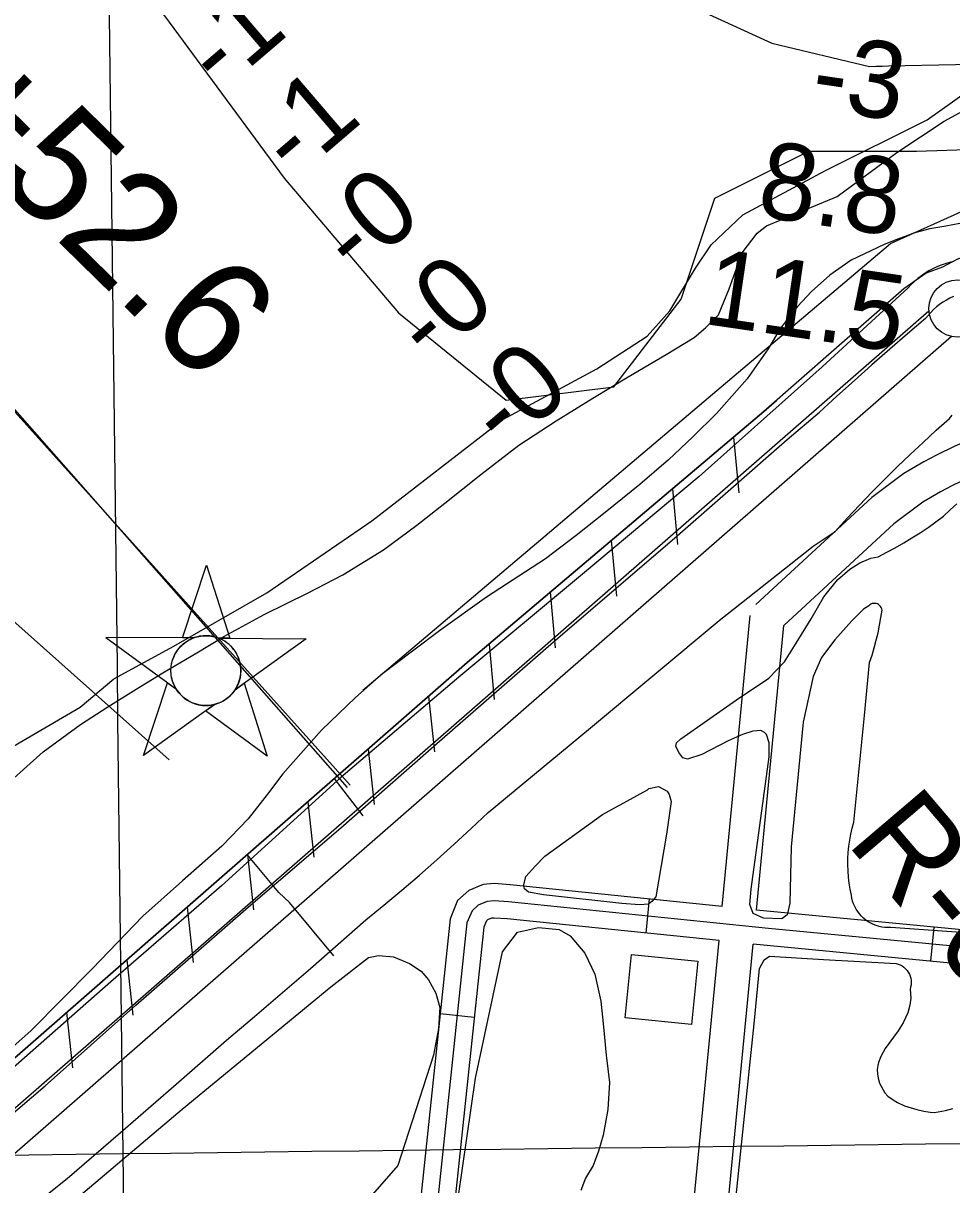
# Model space of a CAD drawing. Extents: x 3704301 to 3742427, y 506229 to 532009.
# Drawn here: x 3713691 to 3714502, y 517742 to 518757 of the extents above; entities that cross this region are included whole.
import ezdxf

# ---------------------------------------------------------------- set-up
doc = ezdxf.new("R2010")
doc.units = 0
for name, color, linetype in [('V-BLDG-OTLN', 7, 'Continuous'), ('V-CHAN-NAID', 7, 'Continuous'), ('V-FLOD-BASE', 7, 'Continuous'), ('V-GRID-MAJR', 7, 'Continuous'), ('V-LEVE-TOET', 7, 'Continuous'), ('V-RIVR-EDGE', 7, 'Continuous'), ('V-RIVR-RANG', 7, 'Continuous'), ('V-RIVR-RANG-IDEN', 7, 'Continuous'), ('V-ROAD-CNTR', 7, 'Continuous'), ('V-RRAP-FSHR', 7, 'Continuous'), ('V-SITE-VEGE', 7, 'Continuous'), ('V-SURV-IDEN', 7, 'Continuous'), ('V-SURV-LINE', 7, 'Continuous'), ('V-TOPO-DPTH', 7, 'Continuous'), ('V-TOPO-MINR', 7, 'Continuous'), ('V-TOPO-WATR', 7, 'Continuous'), ('V-UTIL-LINE', 7, 'Continuous')]:
    doc.layers.add(name, color=color, linetype=linetype)

msp = doc.modelspace()

# ---------------------------------------------------------------- linework, layer by layer
at = {"layer": 'V-BLDG-OTLN'}
msp.add_lwpolyline([(3714280.505, 517937.333), (3714274.965, 517882.015), (3714216.769, 517887.843), (3714222.307, 517943.162)], close=True, dxfattribs=at)
at = {"layer": 'V-CHAN-NAID'}
for points in [[(3713839.534, 518219.94), (3713829.947, 518220.00800000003), (3713851.073, 518283.492), (3713871.2970000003, 518219.715), (3713861.71, 518219.783), (3713860.133, 518220.36100000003), (3713858.038, 518220.981), (3713855.998, 518221.43200000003), (3713853.9620000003, 518221.74), (3713852.795, 518221.854), (3713851.261, 518221.935), (3713849.539, 518221.933), (3713848.169, 518221.863), (3713846.2630000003, 518221.662), (3713844.897, 518221.443), (3713843.113, 518221.059), (3713841.583, 518220.639), (3713840.551, 518220.308)], [(3713839.534, 518219.94), (3713763.043, 518220.482), (3713824.608, 518175.083), (3713823.495, 518176.992), (3713822.685, 518178.62), (3713821.86, 518180.588), (3713821.164, 518182.642), (3713820.799, 518183.965), (3713820.438, 518185.591), (3713820.194, 518187.036), (3713820.006, 518188.634), (3713819.897, 518190.37), (3713819.8850000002, 518191.951), (3713819.992, 518194.025), (3713820.1750000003, 518195.643), (3713820.5670000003, 518197.846), (3713821.048, 518199.76900000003), (3713821.651, 518201.656), (3713822.306, 518203.335), (3713823.0330000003, 518204.923), (3713823.847, 518206.458), (3713824.9080000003, 518208.195), (3713825.9390000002, 518209.66500000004), (3713826.9390000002, 518210.934), (3713827.941, 518212.08), (3713829.25, 518213.417), (3713830.301, 518214.382), (3713832.018, 518215.77900000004), (3713833.23, 518216.64900000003), (3713834.917, 518217.719), (3713836.648, 518218.664), (3713838.094, 518219.348)], [(3713861.71, 518219.783), (3713938.202, 518219.24), (3713875.9990000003, 518174.718), (3713876.91, 518176.207), (3713877.8880000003, 518178.054), (3713878.603, 518179.639), (3713879.342, 518181.594), (3713879.887, 518183.379), (3713880.285, 518185.018), (3713880.646, 518187.028), (3713880.832, 518188.601), (3713880.9560000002, 518190.80700000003), (3713880.926, 518192.869), (3713880.738, 518195.08900000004), (3713880.472, 518196.847), (3713879.981, 518199.079), (3713879.341, 518201.219), (3713878.591, 518203.201), (3713877.943, 518204.64400000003), (3713876.936, 518206.56), (3713875.8740000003, 518208.282), (3713874.66, 518209.984), (3713873.399, 518211.523), (3713872.127, 518212.889), (3713870.495, 518214.42100000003), (3713868.752, 518215.833), (3713867.069, 518217.01), (3713865.182, 518218.142), (3713863.71, 518218.903)], [(3713857.968, 518161.81200000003), (3713795.765, 518117.29000000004), (3713816.8910000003, 518180.773), (3713824.608, 518175.083), (3713825.2430000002, 518174.119), (3713826.626, 518172.26), (3713827.839, 518170.844), (3713829.305, 518169.341), (3713830.694, 518168.09), (3713832.148, 518166.934), (3713833.551, 518165.947), (3713835.2290000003, 518164.911), (3713836.943, 518164), (3713838.734, 518163.189), (3713840.18, 518162.63300000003), (3713841.808, 518162.104), (3713844.034, 518161.54000000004), (3713845.566, 518161.253), (3713847.591, 518160.996), (3713849.128, 518160.892), (3713850.989, 518160.87), (3713852.6780000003, 518160.94800000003), (3713854.3880000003, 518161.124), (3713856.29, 518161.435)], [(3713875.9990000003, 518174.718), (3713883.795, 518180.299), (3713904.019, 518116.522), (3713850.171, 518156.232), (3713857.968, 518161.81200000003), (3713859.634, 518162.288), (3713861.2460000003, 518162.848), (3713863.404, 518163.762), (3713865.139, 518164.646), (3713867.005, 518165.76), (3713868.744, 518166.972), (3713870.296, 518168.217), (3713871.583, 518169.385), (3713872.967, 518170.805), (3713874.171, 518172.207), (3713875.29, 518173.679)]]:
    msp.add_lwpolyline(points, close=True, dxfattribs=at)
msp.add_circle((3713850.4199147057, 518191.4060339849), 30.540600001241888, dxfattribs=at)
at = {"layer": 'V-FLOD-BASE'}
msp.add_line((3714401.961, 518431.208), (3714386.821, 518417.227), dxfattribs=at)
for points in [[(3714503.901, 518518.445), (3714500.72, 518516.979), (3714497.632, 518515.32800000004), (3714494.646, 518513.49700000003), (3714491.772, 518511.496), (3714489.02, 518509.329), (3714486.4, 518507.005), (3714483.92, 518504.531), (3714481.592, 518501.916), (3714479.419, 518499.169), (3714463.698, 518485.843), (3714448.091, 518472.381), (3714432.597, 518458.787), (3714417.219, 518445.061), (3714401.961, 518431.208)], [(3713614.086, 517746.863), (3713709.848, 517828.39400000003), (3713789.091, 517899.015), (3713887.6780000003, 517984.808), (3713968.342, 518054.012), (3714057.023, 518131.746), (3714154.194, 518216.588), (3714259.861, 518307.124), (3714358.4450000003, 518393.39), (3714386.821, 518417.227)]]:
    msp.add_lwpolyline(points, dxfattribs=at)
at = {"layer": 'V-GRID-MAJR'}
for points in [[(3713850.364, 511710.695), (3713778.102, 517769.291), (3713705.816, 523829.819), (3713633.5300000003, 529890.361), (3713633.507, 529892.279)], [(3708498.534, 517706.704), (3713778.102, 517769.291), (3719057.661, 517832.646), (3724337.211, 517896.76900000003), (3729616.752, 517961.659), (3734896.2830000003, 518027.318), (3740175.804, 518093.744), (3740175.805, 518093.744)]]:
    msp.add_spline(points, degree=3, dxfattribs=at)
at = {"layer": 'V-LEVE-TOET'}
for points in [[(3714492.9620000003, 518545.749), (3714489.335, 518544.264), (3714485.792, 518542.591), (3714482.343, 518540.731), (3714479.001, 518538.69200000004), (3714475.767, 518536.476), (3714472.6580000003, 518534.092), (3714469.681, 518531.54600000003), (3714466.84, 518528.847), (3714464.149, 518526), (3714389.018, 518456.804)], [(3714504.241, 518549.016), (3714500.4250000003, 518548.12700000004), (3714496.663, 518547.03500000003), (3714492.9620000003, 518545.749)], [(3714389.018, 518456.804), (3714281.4760000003, 518361.064), (3714181.466, 518277.16000000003), (3714071.5470000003, 518185.668), (3713968.238, 518097.972), (3713863.9990000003, 518003.185), (3713767.298, 517919.288), (3713657.393, 517823.069)], [(3714400.569, 518313.094), (3714411.061, 518324.659), (3714421.71, 518336.079), (3714432.5160000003, 518347.353), (3714443.474, 518358.478), (3714454.585, 518369.451), (3714465.845, 518380.271), (3714477.252, 518390.93700000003), (3714488.805, 518401.445), (3714500.4990000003, 518411.791), (3714502.7430000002, 518414.57)], [(3713673.179, 517702.569), (3713691.721, 517717.755), (3713710.411, 517732.75800000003), (3713729.247, 517747.582), (3713775.853, 517787.614), (3713822.24, 517827.90400000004), (3713868.4020000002, 517868.451), (3713892.997, 517889.199), (3713917.464, 517910.099), (3713941.807, 517931.14400000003), (3713966.02, 517952.33900000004), (3713990.105, 517973.677), (3714005.907, 517986.495), (3714021.543, 517999.515), (3714037.0160000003, 518012.73000000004), (3714052.3170000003, 518026.141), (3714067.4450000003, 518039.746), (3714082.4020000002, 518053.541), (3714097.18, 518067.527), (3714184.832, 518140.05700000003), (3714298.9960000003, 518235.342), (3714381.088, 518300.294), (3714400.569, 518313.094)]]:
    msp.add_lwpolyline(points, dxfattribs=at)
at = {"layer": 'V-RIVR-EDGE'}
msp.add_lwpolyline([(3713663.058686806, 518114.16552429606), (3713740.613165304, 518159.59857843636), (3713770.08985192, 518184.1390829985), (3713822.389202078, 518212.82544010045), (3713903.548587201, 518259.4502336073), (3713995.553865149, 518322.25702741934), (3714109.83492302, 518410.8227848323), (3714192.189016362, 518455.0433176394), (3714236.083845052, 518483.75045670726), (3714255.949426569, 518505.91342024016), (3714278.25341059, 518543.0785201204), (3714292.111309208, 518563.4553590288), (3714319.7914802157, 518589.8012857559), (3714391.926723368, 518628.6441471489), (3714480.884369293, 518672.8483512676), (3714527.1908808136, 518705.7518133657), (3714592.1029508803, 518736.808289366), (3714644.9833264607, 518757.68896353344)], dxfattribs=at)
at = {"layer": 'V-ROAD-CNTR'}
for p, q in [((3714235.1894906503, 517961.969049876), (3714238.2454845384, 517991.8129901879)), ((3714484.0729928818, 517937.40209901), (3714486.939987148, 517967.265039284)), ((3714085.00979101, 517888.21919737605), (3714055.1748506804, 517891.36019109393))]:
    msp.add_line(p, q, dxfattribs=at)
for points in [[(3715084.1797926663, 518468.53703673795), (3714839.3422823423, 518438.433096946), (3714653.624653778, 518425.268123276), (3714635.862689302, 518423.7071263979), (3714619.9017212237, 518421.65613049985), (3714600.441760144, 518418.315137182), (3714584.0347929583, 518414.76614428), (3714566.069828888, 518410.0871536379), (3714555.014850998, 518406.78616023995), (3714540.1858806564, 518401.838170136), (3714521.4529181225, 518394.697184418), (3714505.1089508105, 518387.6171985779), (3714488.981983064, 518379.80921419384), (3714477.9370051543, 518373.96522588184), (3714460.407040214, 518363.82424616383), (3714432.547095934, 518342.70728839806), (3714331.0492989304, 518249.1234755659)], [(3714825.8863092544, 518407.404159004), (3714655.99864903, 518395.36218308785), (3714639.08868285, 518393.8751860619), (3714624.3537123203, 518391.982189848), (3714606.1537487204, 518388.85719609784), (3714590.990779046, 518385.57620265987), (3714574.14381274, 518381.18921143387), (3714564.0568329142, 518378.17821745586), (3714550.2818604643, 518373.5802266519), (3714532.762895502, 518366.903240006), (3714517.6129258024, 518360.34125313), (3714502.5379559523, 518353.04126773), (3714492.4689760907, 518347.71327838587), (3714477.0430069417, 518338.790296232), (3714451.8210573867, 518319.6713344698), (3714355.598249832, 518230.95151190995)], [(3714301.781357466, 517985.3070031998), (3714326.2863084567, 518239.53449474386)], [(3714331.6192977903, 517982.17500946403), (3714355.598249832, 518230.95151190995)], [(3714301.781357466, 517985.3070031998), (3714116.2937284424, 518004.30196520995), (3714102.251756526, 518005.25796329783), (3714092.82977537, 518004.48196485), (3714080.307800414, 517999.34897511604), (3714070.435820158, 517990.3749930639), (3714063.9338331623, 517974.581024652), (3714036.2598885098, 517711.6615504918)], [(3715033.26789449, 517903.01216779), (3714888.08318486, 517913.93414594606), (3714759.820441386, 517926.00112181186), (3714342.0352769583, 517966.1060416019), (3714115.0197309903, 517989.353995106), (3714102.3587563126, 517990.215993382), (3714096.372768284, 517989.7229943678), (3714088.4417841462, 517986.47200087), (3714083.021794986, 517981.5450107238), (3714078.6258037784, 517970.86603208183), (3714051.177858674, 517710.09155363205)], [(3714298.9033632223, 517955.4440629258), (3714113.745733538, 517974.406025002), (3714102.465756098, 517975.1740234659), (3714099.915761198, 517974.96402388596), (3714096.575767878, 517973.595026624), (3714095.6077698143, 517972.715028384), (3714093.317774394, 517967.15103951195), (3714066.0958288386, 517708.521556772)], [(3714780.0354009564, 517939.165095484), (3714761.239438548, 517940.9340919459), (3714331.6192977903, 517982.17500946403)], [(3714214.8315313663, 516863.4722468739), (3714201.6745576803, 516901.517170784), (3714201.1185587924, 516916.40414100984), (3714201.8425573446, 516948.47907685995), (3714298.9033632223, 517955.4440629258)], [(3714243.183474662, 516873.278227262), (3714231.4864980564, 516907.101159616), (3714231.130498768, 516916.6261405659), (3714231.810497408, 516946.69908042), (3714328.740303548, 517952.31306918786)], [(3714777.1134068, 517909.3081551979), (3714758.4014442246, 517911.06815167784), (3714328.740303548, 517952.31306918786)]]:
    msp.add_lwpolyline(points, dxfattribs=at)
at = {"layer": 'V-RRAP-FSHR'}
for p, q in [((3714311.649, 518395.534), (3714316.105, 518346.907)), ((3714258.2120000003, 518350.318), (3714262.668, 518301.691)), ((3714204.774, 518305.103), (3714209.231, 518256.476)), ((3714151.3370000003, 518259.887), (3714155.794, 518211.26)), ((3714097.9, 518214.67100000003), (3714102.356, 518166.044)), ((3714044.921, 518168.923), (3714050.1380000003, 518120.371)), ((3713992.198, 518122.876), (3713997.415, 518074.325)), ((3713939.474, 518076.83), (3713944.691, 518028.278)), ((3713886.751, 518030.783), (3713891.968, 517982.232)), ((3713834.028, 517984.737), (3713839.245, 517936.186)), ((3713781.306, 517938.69), (3713786.524, 517890.139)), ((3713728.5840000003, 517892.642), (3713733.8030000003, 517844.091))]:
    msp.add_line(p, q, dxfattribs=at)
for points in [[(3713987.6284698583, 518174.2519979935), (3714448.770486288, 518564.7359663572), (3714742.224310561, 518696.92822248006), (3715881.889207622, 518753.2748465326), (3716266.2537519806, 518793.8989745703), (3716843.0852405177, 518890.7407026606), (3717110.3349047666, 518911.17564667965), (3717741.270457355, 518924.00227069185), (3718486.4311620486, 518954.9455027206), (3719294.778810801, 519011.24502277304), (3719786.2598992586, 519085.7553588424), (3720431.328699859, 519110.59350286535), (3720895.931836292, 519113.0777268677), (3721218.4652125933, 519068.37193482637), (3721397.6508767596, 519012.4881587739), (3721721.322941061, 518965.4353587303), (3721950.5678692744, 518904.45001467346), (3722606.869949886, 518712.51759849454), (3722865.6920941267, 518669.46659045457), (3723100.4830063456, 518674.84873445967), (3723533.3831027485, 518647.1433904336), (3724154.011071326, 518572.98531036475), (3724673.74841581, 518469.1639982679)], [(3715662.773, 518669.53), (3715159.5640000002, 518603.26900000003), (3715020.8200000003, 518585.764), (3714913.2490000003, 518575.071), (3714796.3540000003, 518570.006), (3714535.998, 518557.253), (3714516.403, 518554.038), (3714507.449, 518551.094), (3714494.148, 518543.95), (3714479.898, 518538.666), (3714460.327, 518525.081), (3714338.0530000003, 518417.876), (3714078.748, 518198.466), (3713802.054, 517956.81200000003), (3713566.471, 517751.049)], [(3713566.471, 517751.049), (3713802.054, 517956.81200000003), (3714078.748, 518198.466), (3714338.0530000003, 518417.876), (3714349.13, 518427.588)]]:
    msp.add_lwpolyline(points, dxfattribs=at)
at = {"layer": 'V-SITE-VEGE'}
for points in [[(3713679.779, 518094.73000000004), (3713708.261, 518120.365), (3713740.91, 518144.232), (3713764.661, 518159.75), (3713789.597, 518175.272), (3713812.756, 518189.598), (3713842.448, 518206.914), (3713866.198, 518221.24100000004), (3713901.238, 518240.35500000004), (3713939.845, 518259.477), (3713970.137, 518275.01), (3714005.761, 518297.097), (3714034.849, 518318.575), (3714059.184, 518337.662), (3714090.6410000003, 518362.713), (3714123.882, 518388.362), (3714156.535, 518409.848), (3714188.6010000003, 518429.547), (3714219.478, 518448.055), (3714252.7320000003, 518467.759), (3714277.076, 518482.685), (3714287.167, 518491.03500000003), (3714298.437, 518502.358), (3714307.897, 518524.978), (3714319.122, 518556.523), (3714332.161, 518573.798), (3714340.3170000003, 518580.297), (3714402.156, 518605.87200000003), (3714454.468, 518644.211), (3714495.727, 518671.73000000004), (3714522.4, 518686.256)], [(3714509.397, 518582.181), (3714497.284, 518579.94200000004), (3714483.3200000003, 518577.556), (3714474.397, 518575.289), (3714469.009, 518573.661), (3714461.761, 518570.876), (3714455.865, 518568.916), (3714443.386, 518563.956), (3714414.282, 518550.207), (3714395.879, 518537.082), (3714379.8570000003, 518522.772), (3714367.401, 518509.659), (3714352.58, 518490.594), (3714341.918, 518472.73000000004), (3714323.548, 518446.521), (3714296.86, 518416.129), (3714276.095, 518395.862), (3714254.737, 518375.593), (3714229.813, 518354.126), (3714199.543, 518329.673), (3714174.021, 518309.393), (3714147.309, 518289.11), (3714095.654, 518255.68700000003), (3714055.88, 518227.047), (3714030.95, 518208.554), (3714003.646, 518187.675), (3713981.093, 518167.99700000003), (3713951.43, 518139.38300000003), (3713917.626, 518101.245), (3713905.1780000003, 518084.564), (3713887.393, 518061.925), (3713864.257, 518038.083), (3713829.84, 518007.67600000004), (3713795.426, 517976.669), (3713750.935, 517930.773), (3713697.546, 517876.532), (3713609.127, 517798.42100000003)], [(3714481.586, 518316.606), (3714488.446, 518321.489), (3714495.186, 518326.537), (3714500.892, 518331.895), (3714506.739, 518337.097)], [(3714448.971, 517966.88800000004), (3714446.401, 517966.816), (3714443.8310000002, 517966.949), (3714441.281, 517967.287), (3714438.7660000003, 517967.824), (3714436.3000000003, 517968.559), (3714433.9020000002, 517969.489), (3714431.5840000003, 517970.60500000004), (3714429.362, 517971.901), (3714427.248, 517973.37), (3714425.259, 517975), (3714423.406, 517976.784), (3714421.7, 517978.70900000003), (3714420.1520000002, 517980.76300000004), (3714418.773, 517982.934), (3714417.5670000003, 517985.207), (3714416.549, 517987.569), (3714415.72, 517990.004), (3714415.0870000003, 517992.494), (3714414.653, 517995.032), (3714413.569, 518000.305), (3714412.711, 518005.624), (3714412.083, 518010.971), (3714411.683, 518016.343), (3714411.515, 518021.72500000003), (3714411.579, 518027.11100000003), (3714411.872, 518032.487), (3714412.396, 518037.847), (3714413.148, 518043.18), (3714414.127, 518048.476), (3714415.333, 518053.72500000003), (3714416.762, 518058.919), (3714421.477, 518105.474), (3714426.052, 518152.04600000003), (3714430.494, 518198.629), (3714432.647, 518205.011), (3714434.6040000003, 518211.454), (3714436.37, 518217.952), (3714437.9390000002, 518224.50200000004), (3714439.309, 518231.092), (3714440.4820000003, 518237.724), (3714441.453, 518244.38800000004), (3714441.179, 518245.52400000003), (3714440.718, 518246.60000000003), (3714440.0810000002, 518247.583), (3714439.29, 518248.443), (3714438.367, 518249.15400000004), (3714437.3370000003, 518249.696), (3714436.233, 518250.055), (3714435.082, 518250.221), (3714433.927, 518250.186), (3714432.794, 518249.952), (3714431.719, 518249.526), (3714430.7320000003, 518248.924), (3714429.863, 518248.156), (3714425.112, 518245.17), (3714415.0300000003, 518235.039), (3714400.202, 518218.352), (3714388.346, 518202.863), (3714381.25, 518186.196), (3714372.4250000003, 518146.332), (3714361.9820000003, 518037.487), (3714360.909, 517988.128), (3714358.556, 517978.01300000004), (3714353.807, 517974.433), (3714337.75, 517974.99), (3714328.819, 517979.131), (3714325.829, 517986.854), (3714326.9820000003, 518000.532), (3714342.7660000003, 518115.933), (3714342.735, 518128.422), (3714340.339, 518135.553), (3714338.551, 518137.333), (3714335.573, 518139.108), (3714328.438, 518138.496), (3714319.5270000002, 518135.50200000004), (3714307.0530000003, 518130.12200000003), (3714283.8880000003, 518118.172), (3714271.412, 518113.979), (3714267.2460000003, 518115.159), (3714263.666, 518119.908), (3714261.274, 518125.254), (3714261.864, 518128.229), (3714265.421, 518131.805), (3714314.1, 518165.816), (3714342.6, 518184.914), (3714356.244, 518199.217), (3714366.3140000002, 518215.298), (3714379.345, 518236.73600000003), (3714390.597, 518255.793), (3714402.455, 518270.686), (3714413.137, 518280.228), (3714422.042, 518285.604), (3714431.549, 518289.786), (3714438.086, 518290.99), (3714445.592, 518294.81), (3714453, 518298.811), (3714460.309, 518302.993), (3714467.512, 518307.356), (3714474.606, 518311.89400000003), (3714481.586, 518316.606)], [(3714070.867, 517730.278), (3714086.191, 517835.28500000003), (3714109.573, 517945.503), (3714122.796, 517962.837), (3714141.245, 517966.919), (3714159.128, 517965.229), (3714168.946, 517959.48600000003), (3714181.67, 517944.522), (3714190.366, 517926.08400000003), (3714195.613, 517902.452), (3714197.974, 517879.963), (3714200.342, 517855.167), (3714203.281, 517831.527), (3714201.608, 517807.875), (3714197.6240000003, 517785.374), (3714193.6180000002, 517771.521), (3714189.037, 517758.82300000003), (3714182.1410000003, 517747.846), (3714178.129, 517736.879)], [(3714579.234, 517957.434), (3714448.971, 517966.88800000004)], [(3713589.579, 517601.086), (3713705.267, 517702.87200000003), (3713829.597, 517808.141), (3713959.688, 517915.151), (3713992.503, 517940.606), (3714001.149, 517942.359), (3714014.418, 517941.237), (3714028.273, 517935.50200000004), (3714038.673, 517928.607), (3714045.034, 517921.123), (3714051.4050000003, 517909.603), (3714054.897, 517896.924), (3714053.787, 517878.466), (3714049.228, 517855.382), (3714018.3140000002, 517758.989), (3713987.829, 517724.313)], [(3714305.904, 517615.148), (3714304.679, 517630.01), (3714313.367, 517726.95900000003), (3714329.644, 517882.797), (3714334.287, 517930.974), (3714338.43, 517938.716), (3714343.182, 517941.702), (3714390.167, 517938.841), (3714453.802, 517935.424)], [(3714453.802, 517935.424), (3714455.625, 517934.906), (3714457.38, 517934.181), (3714459.043, 517933.256), (3714460.592, 517932.137), (3714462.007, 517930.851), (3714463.268, 517929.407), (3714464.362, 517927.822), (3714465.271, 517926.12200000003), (3714465.986, 517924.324), (3714466.4960000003, 517922.45900000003), (3714466.795, 517920.544), (3714466.879, 517918.604), (3714466.7460000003, 517916.67100000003), (3714466.4, 517914.762), (3714465.843, 517912.907), (3714466.471, 517905.077), (3714465.64, 517899.04000000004), (3714463.889, 517892.445), (3714459.801, 517883.696), (3714455.5130000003, 517876.495), (3714444.117, 517860.996), (3714442.332, 517858.059), (3714440.394, 517854), (3714438.305, 517848.749), (3714437.722, 517846.293), (3714437.267, 517842.853), (3714437.441, 517838.912), (3714437.965, 517835.11100000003), (3714439.262, 517830.88), (3714443.964, 517822.469), (3714446.536, 517819.422), (3714451.005, 517816.284), (3714454.779, 517813.929), (3714461.0810000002, 517811.129), (3714471.737, 517807.865), (3714477.907, 517806.259), (3714483.451, 517805.434), (3714487.179, 517805.25800000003), (3714496.757, 517806.994), (3714503.239, 517808.621)]]:
    msp.add_lwpolyline(points, dxfattribs=at)
msp.add_lwpolyline([(3714236.3910000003, 518087.136), (3714237.577, 518088.32800000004), (3714245.898, 518090.132), (3714253.637, 518085.989), (3714255.429, 518083.02), (3714257.227, 518077.076), (3714253.133, 518048.523), (3714243.7490000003, 517993.792), (3714240.1920000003, 517989.623), (3714237.222, 517987.237), (3714229.495, 517986.62200000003), (3714214.031, 517987.775), (3714145.628, 517995.343), (3714132.539, 517997.69), (3714128.963, 518000.655), (3714128.361, 518004.221), (3714130.128, 518011.36), (3714138.431, 518020.896), (3714146.736, 518029.24100000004), (3714197.194, 518065.634)], close=True, dxfattribs=at)
at = {"layer": 'V-SURV-LINE'}
for points in [[(3713051.7608847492, 517258.382569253), (3714482.3907191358, 518506.01785153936)], [(3714502.117087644, 518483.41540667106), (3713071.486975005, 517235.77988172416)]]:
    msp.add_lwpolyline(points, dxfattribs=at)
msp.add_circle((3714507.30915, 518507.8465), 25, dxfattribs=at)
at = {"layer": 'V-TOPO-DPTH'}
msp.add_lwpolyline([(3713587.021733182, 519043.65553555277), (3713771.825801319, 518821.81168978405), (3713918.8474414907, 518621.86225915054), (3714018.822156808, 518504.2449470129), (3714112.9160065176, 518427.79369412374), (3714207.0098562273, 518439.55542533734), (3714265.8185122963, 518516.0066782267), (3714295.2228403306, 518604.21966232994), (3714377.5549588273, 518645.3857215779), (3714471.6488085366, 518645.3857215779), (3714824.5007449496, 518657.1474527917), (3715289.089127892, 518657.1474527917), (3715788.9627044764, 518680.67091521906), (3716175.726390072, 518774.95598747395)], dxfattribs=at)
at = {"layer": 'V-TOPO-MINR'}
msp.add_lwpolyline([(3713519.1199563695, 519118.0668612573), (3714345.1427280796, 518739.933031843), (3714430.465417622, 518719.4783097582), (3714436.0398192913, 518719.65269711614), (3714441.615051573, 518719.79812722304), (3714447.1908375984, 518719.92425249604), (3714812.791253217, 518727.2442410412), (3714918.9639521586, 518729.1005942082), (3715025.14080406, 518730.59782749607), (3715131.323885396, 518731.55638096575), (3715237.511119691, 518732.15581455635), (3715330.240496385, 518732.4440506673), (3715900.2487051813, 518758.1688842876)], dxfattribs=at)
at = {"layer": 'V-TOPO-WATR'}
msp.add_lwpolyline([(3713587.021733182, 519043.65553555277), (3713771.825801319, 518821.81168978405), (3713918.8474414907, 518621.86225915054), (3714018.822156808, 518504.2449470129), (3714112.9160065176, 518427.79369412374), (3714207.0098562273, 518439.55542533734), (3714265.8185122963, 518516.0066782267), (3714295.2228403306, 518604.21966232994), (3714377.5549588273, 518645.3857215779), (3714471.6488085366, 518645.3857215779), (3714824.5007449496, 518657.1474527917), (3715289.089127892, 518657.1474527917), (3715788.9627044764, 518680.67091521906), (3716175.726390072, 518774.95598747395)], dxfattribs=at)
at = {"layer": 'V-UTIL-LINE'}
for p, q in [((3713379.291, 518756.357), (3713976.438, 518091.181)), ((3713387.751, 518754.827), (3713973.878, 518089.264)), ((3713322.586, 518554.43), (3713818.359, 518113.41000000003)), ((3713987.872, 518064.506), (3713962.416, 518097.319)), ((3713962.211, 517942.17100000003), (3713923.4560000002, 517988.795))]:
    msp.add_line(p, q, dxfattribs=at)
msp.add_lwpolyline([(3713923.4560000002, 517988.795), (3713914.208, 517997.42600000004), (3713886.443, 518030.81)], dxfattribs=at)

# ---------------------------------------------------------------- texts
at = {"layer": 'V-RIVR-RANG'}
for s, rotation, p in [('-1', 40.54750000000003, (3713863.163004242, 518696.13048388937)), ('-3', 351.66832571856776, (3714377.659627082, 518683.11584203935)), ('-1', 40.54750000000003, (3713927.982004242, 518619.9824838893)), ('8.8', 351.66832571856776, (3714330.7971827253, 518588.9116545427)), ('-0', 40.54750000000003, (3713981.5755078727, 518534.23075356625)), ('11.5', 351.66832571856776, (3714283.6727428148, 518494.7466895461)), ('-0', 40.54750000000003, (3714046.3935078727, 518458.0817535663)), ('-0', 40.54750000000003, (3714111.2115078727, 518381.9337535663))]:
    msp.add_text(s, height=66.99999999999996, rotation=rotation, dxfattribs=at).set_placement(p)
at = {"layer": 'V-RIVR-RANG-IDEN'}
msp.add_text('R-0+00', height=82.99999799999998, rotation=310.4046315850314, dxfattribs=at).set_placement((3714409.287, 518041.153))
at = {"layer": 'V-SURV-IDEN'}
msp.add_text('364+52.6', height=100.0000000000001, rotation=315.5768516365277, dxfattribs=at).set_placement((3713449.1166480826, 518833.0146524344))

doc.saveas('drawing.dxf')
